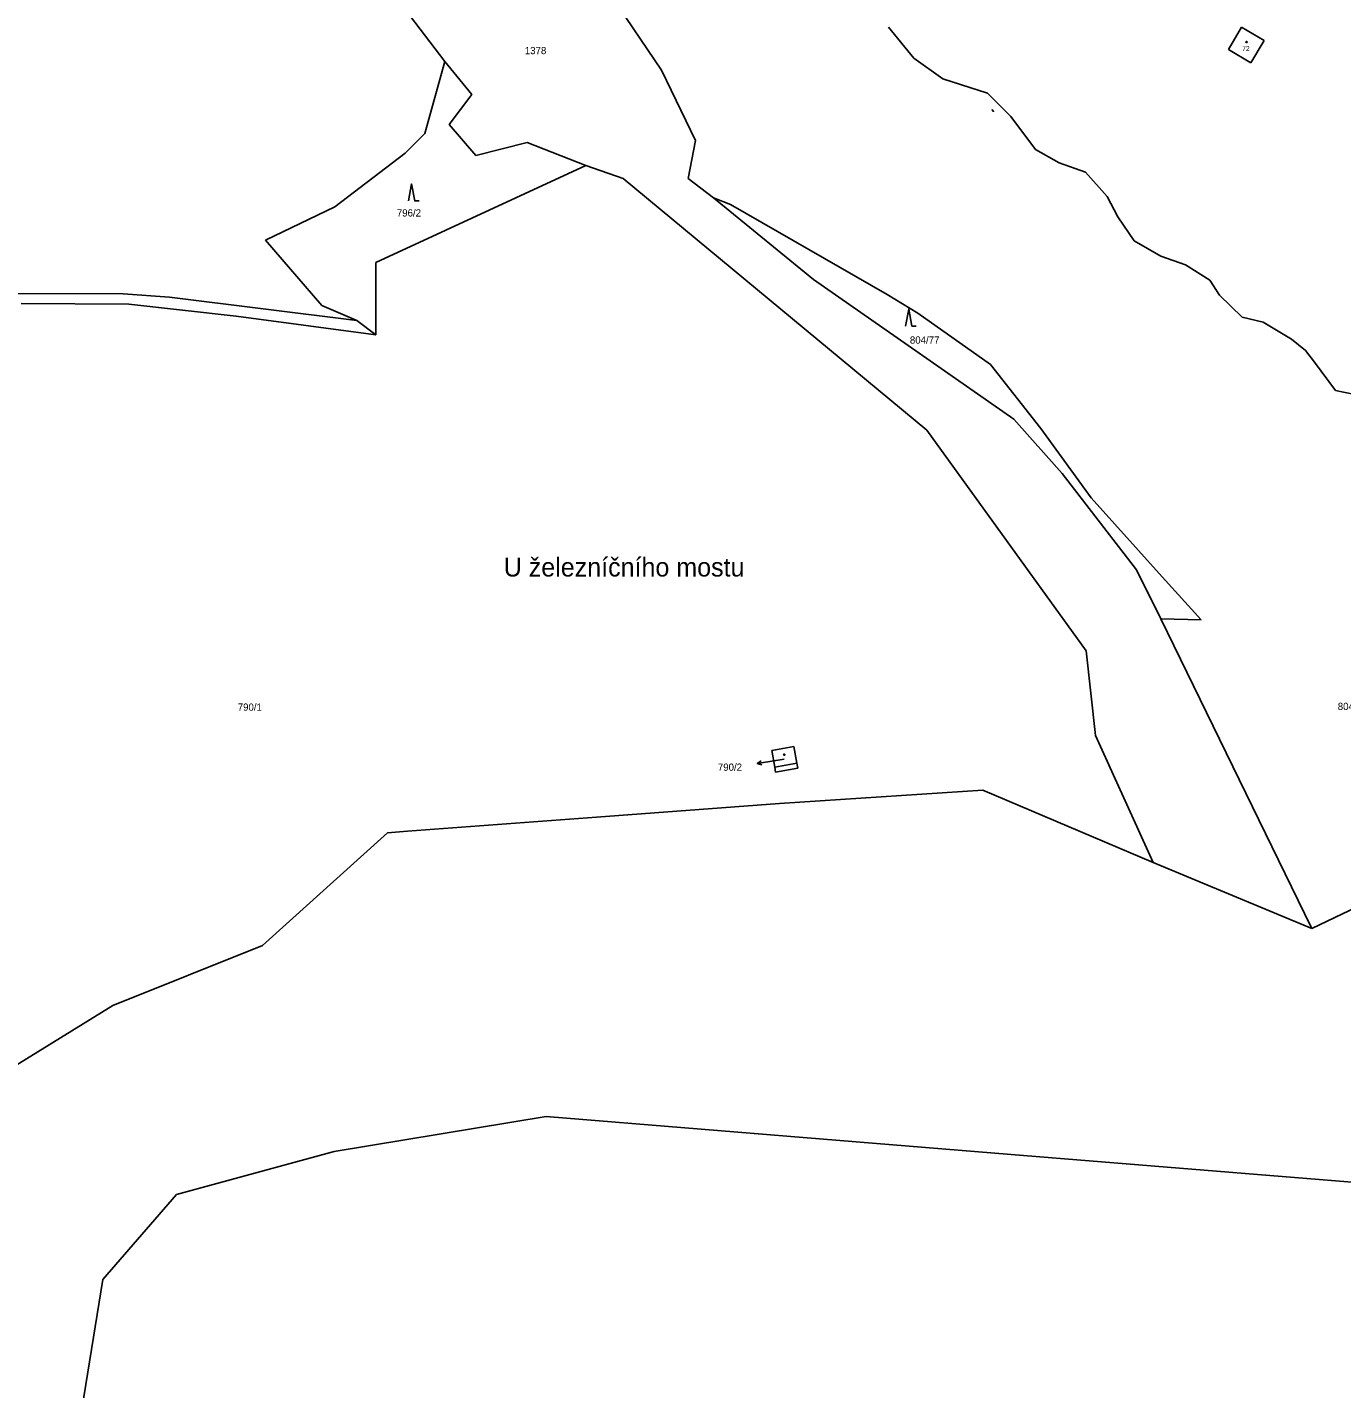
# Model space of a CAD drawing. Extents: x -852001 to -842497, y -1063614 to -1052182.
# Drawn here: x -843659.2 to -843350.2, y -1062182 to -1061862.1 of the extents above; entities that cross this region are included whole.
import ezdxf

# ---------------------------------------------------------------- set-up
doc = ezdxf.new("R2010")
doc.units = 0
for name, color, linetype in [('Default', 7, 'Continuous'), ('KN_HRANICE', 7, 'Continuous'), ('KN_KULTURY', 7, 'Continuous'), ('KN_PARCELY', 7, 'Continuous'), ('KN_SLUCKY', 7, 'Continuous')]:
    doc.layers.add(name, color=color, linetype=linetype)

# ---------------------------------------------------------------- blocks, each defined once
blk = doc.blocks.new('308')
at = {"layer": 'Default'}
blk.add_lwpolyline([(-0.75, 0), (0, 4), (0.75, 0), (1.75, 0)], dxfattribs=at)
blk = doc.blocks.new('10292')
at = {"layer": 'Default'}
blk.add_line((0, 3), (0, 0), dxfattribs=at)
blk.add_lwpolyline([(-0.5, 2), (0, 3), (0.5, 2)], dxfattribs=at)
blk = doc.blocks.new('1060')
at = {"layer": 'Default'}
blk.add_line((-0.3, 0), (0.3, 0), dxfattribs=at)
blk.add_lwpolyline([(0.18, 0.04), (0.3, 0), (0.18, -0.04)], dxfattribs=at)
blk = doc.blocks.new('402')
at = {"layer": 'Default'}
blk.add_lwpolyline([(0.09, 0.15), (0.18, 0), (0.09, -0.15), (-0.09, -0.15), (-0.18, 0), (-0.09, 0.15), (0.09, 0.15)], dxfattribs=at)

msp = doc.modelspace()

# ---------------------------------------------------------------- linework, layer by layer
at = {"layer": 'KN_HRANICE'}
for p, q in [((-843575.5, -1061851.1), (-843561, -1061870.14)), ((-843575.5, -1061851.1), (-843561, -1061870.14)), ((-843510.14, -1061872.13), (-843523.95, -1061851.73)), ((-843510.14, -1061872.13), (-843523.95, -1061851.73)), ((-843373.8, -1061862.07), (-843376.87, -1061867.27)), ((-843373.8, -1061862.07), (-843376.87, -1061867.27)), ((-843368.5, -1061865.2), (-843373.8, -1061862.07)), ((-843368.5, -1061865.2), (-843373.8, -1061862.07)), ((-843371.59, -1061870.39), (-843368.5, -1061865.2)), ((-843371.59, -1061870.39), (-843368.5, -1061865.2)), ((-843376.87, -1061867.27), (-843371.59, -1061870.39)), ((-843376.87, -1061867.27), (-843371.59, -1061870.39)), ((-843561, -1061870.14), (-843565.72, -1061887.02)), ((-843561, -1061870.14), (-843565.72, -1061887.02)), ((-843561, -1061870.14), (-843554.72, -1061877.9)), ((-843561, -1061870.14), (-843554.72, -1061877.9)), ((-843502.1, -1061888.66), (-843510.14, -1061872.13)), ((-843502.1, -1061888.66), (-843510.14, -1061872.13)), ((-843554.72, -1061877.9), (-843560.02, -1061884.93)), ((-843554.72, -1061877.9), (-843560.02, -1061884.93)), ((-843565.72, -1061887.02), (-843570.36, -1061891.66)), ((-843565.72, -1061887.02), (-843570.36, -1061891.66)), ((-843560.02, -1061884.93), (-843553.73, -1061892.2)), ((-843560.02, -1061884.93), (-843553.73, -1061892.2)), ((-843553.73, -1061892.2), (-843541.66, -1061889.12)), ((-843553.73, -1061892.2), (-843541.66, -1061889.12)), ((-843541.66, -1061889.12), (-843527.86, -1061894.54)), ((-843541.66, -1061889.12), (-843527.86, -1061894.54)), ((-843503.85, -1061897.57), (-843502.1, -1061888.66)), ((-843503.85, -1061897.57), (-843502.1, -1061888.66)), ((-843570.36, -1061891.66), (-843586.92, -1061904.25)), ((-843570.36, -1061891.66), (-843586.92, -1061904.25)), ((-843577.25, -1061917.38), (-843527.86, -1061894.54)), ((-843577.25, -1061917.38), (-843527.86, -1061894.54)), ((-843527.86, -1061894.54), (-843519.11, -1061897.62)), ((-843527.86, -1061894.54), (-843519.11, -1061897.62)), ((-843497.88, -1061902.17), (-843503.85, -1061897.57)), ((-843497.88, -1061902.17), (-843503.85, -1061897.57)), ((-843519.11, -1061897.62), (-843447.74, -1061956.71)), ((-843519.11, -1061897.62), (-843447.74, -1061956.71)), ((-843474.38, -1061921.33), (-843497.88, -1061902.17)), ((-843497.88, -1061902.17), (-843493.89, -1061903.71)), ((-843474.38, -1061921.33), (-843497.88, -1061902.17)), ((-843497.88, -1061902.17), (-843493.89, -1061903.71)), ((-843493.89, -1061903.71), (-843457.08, -1061924.86)), ((-843493.89, -1061903.71), (-843457.08, -1061924.86)), ((-843586.92, -1061904.25), (-843603.22, -1061912.07)), ((-843586.92, -1061904.25), (-843603.22, -1061912.07)), ((-843603.22, -1061912.07), (-843589.97, -1061927.45)), ((-843603.22, -1061912.07), (-843589.97, -1061927.45)), ((-843577.26, -1061934.32), (-843577.25, -1061917.38)), ((-843577.26, -1061934.32), (-843577.25, -1061917.38)), ((-843427.27, -1061954.14), (-843474.38, -1061921.33)), ((-843427.27, -1061954.14), (-843474.38, -1061921.33)), ((-843636.67, -1061924.71), (-843677.25, -1061924.62)), ((-843636.67, -1061924.71), (-843677.25, -1061924.62)), ((-843625.73, -1061925.47), (-843636.67, -1061924.71)), ((-843625.73, -1061925.47), (-843636.67, -1061924.71)), ((-843581.73, -1061930.99), (-843625.73, -1061925.47)), ((-843581.73, -1061930.99), (-843625.73, -1061925.47)), ((-843457.08, -1061924.86), (-843449.87, -1061929.22)), ((-843457.08, -1061924.86), (-843449.87, -1061929.22)), ((-843660.62, -1061927.01), (-843635.34, -1061927.1)), ((-843660.62, -1061927.01), (-843635.34, -1061927.1)), ((-843635.34, -1061927.1), (-843610.04, -1061929.96)), ((-843635.34, -1061927.1), (-843610.04, -1061929.96)), ((-843589.97, -1061927.45), (-843581.73, -1061930.99)), ((-843589.97, -1061927.45), (-843581.73, -1061930.99)), ((-843449.87, -1061929.22), (-843432.83, -1061941.28)), ((-843449.87, -1061929.22), (-843432.83, -1061941.28)), ((-843610.04, -1061929.96), (-843577.26, -1061934.32)), ((-843610.04, -1061929.96), (-843577.26, -1061934.32)), ((-843577.26, -1061934.32), (-843581.73, -1061930.99)), ((-843577.26, -1061934.32), (-843581.73, -1061930.99)), ((-843432.83, -1061941.28), (-843420.93, -1061956.38)), ((-843432.83, -1061941.28), (-843420.93, -1061956.38)), ((-843415.95, -1061966.96), (-843427.27, -1061954.14)), ((-843415.95, -1061966.96), (-843427.27, -1061954.14)), ((-843447.74, -1061956.71), (-843410.34, -1062008.61)), ((-843447.74, -1061956.71), (-843410.34, -1062008.61)), ((-843420.93, -1061956.38), (-843409.12, -1061972.68)), ((-843420.93, -1061956.38), (-843409.12, -1061972.68)), ((-843398.44, -1061989.53), (-843415.95, -1061966.96)), ((-843398.44, -1061989.53), (-843415.95, -1061966.96)), ((-843409.12, -1061972.68), (-843392.46, -1061991.22)), ((-843409.12, -1061972.68), (-843392.46, -1061991.22)), ((-843392.79, -1062001.1), (-843398.44, -1061989.53)), ((-843392.79, -1062001.1), (-843398.44, -1061989.53)), ((-843392.46, -1061991.22), (-843383.26, -1062001.29)), ((-843392.46, -1061991.22), (-843383.26, -1062001.29)), ((-843357.43, -1062073.51), (-843392.79, -1062001.1)), ((-843383.26, -1062001.29), (-843392.79, -1062001.1)), ((-843357.43, -1062073.51), (-843392.79, -1062001.1)), ((-843383.26, -1062001.29), (-843392.79, -1062001.1)), ((-843410.34, -1062008.61), (-843408.1, -1062028.48)), ((-843410.34, -1062008.61), (-843408.1, -1062028.48)), ((-843408.1, -1062028.48), (-843394.55, -1062058.3)), ((-843408.1, -1062028.48), (-843394.55, -1062058.3)), ((-843484.2, -1062031.99), (-843478.99, -1062031.04)), ((-843484.2, -1062031.99), (-843478.99, -1062031.04)), ((-843478.99, -1062031.04), (-843478.31, -1062034.99)), ((-843478.99, -1062031.04), (-843478.31, -1062034.99)), ((-843483.48, -1062035.92), (-843484.2, -1062031.99)), ((-843483.48, -1062035.92), (-843484.2, -1062031.99)), ((-843478.31, -1062034.99), (-843478.1, -1062036.2)), ((-843478.31, -1062034.99), (-843478.1, -1062036.2)), ((-843483.29, -1062037.13), (-843483.48, -1062035.92)), ((-843483.29, -1062037.13), (-843483.48, -1062035.92)), ((-843478.1, -1062036.2), (-843483.29, -1062037.13)), ((-843478.1, -1062036.2), (-843483.29, -1062037.13)), ((-843434.57, -1062041.33), (-843482.38, -1062044.5)), ((-843434.57, -1062041.33), (-843482.38, -1062044.5)), ((-843394.55, -1062058.3), (-843434.57, -1062041.33)), ((-843394.55, -1062058.3), (-843434.57, -1062041.33)), ((-843482.38, -1062044.5), (-843525.38, -1062047.66)), ((-843482.38, -1062044.5), (-843525.38, -1062047.66)), ((-843525.38, -1062047.66), (-843569.83, -1062051)), ((-843525.38, -1062047.66), (-843569.83, -1062051)), ((-843569.83, -1062051), (-843574.5, -1062051.35)), ((-843569.83, -1062051), (-843574.5, -1062051.35)), ((-843304, -1062048.33), (-843357.26, -1062073.88)), ((-843304, -1062048.33), (-843357.26, -1062073.88)), ((-843574.5, -1062051.35), (-843603.92, -1062077.87)), ((-843574.5, -1062051.35), (-843603.92, -1062077.87)), ((-843357.26, -1062073.88), (-843394.55, -1062058.3)), ((-843357.26, -1062073.88), (-843394.55, -1062058.3)), ((-843357.26, -1062073.88), (-843357.43, -1062073.51)), ((-843357.26, -1062073.88), (-843357.43, -1062073.51)), ((-843603.92, -1062077.87), (-843639.07, -1062091.95)), ((-843603.92, -1062077.87), (-843639.07, -1062091.95)), ((-843639.07, -1062091.95), (-843668.06, -1062109.81)), ((-843639.07, -1062091.95), (-843668.06, -1062109.81)), ((-843587.08, -1062126.23), (-843537.23, -1062118.05)), ((-843587.08, -1062126.23), (-843537.23, -1062118.05)), ((-843537.23, -1062118.05), (-843427.91, -1062126.94)), ((-843537.23, -1062118.05), (-843427.91, -1062126.94)), ((-843624.14, -1062136.31), (-843587.08, -1062126.23)), ((-843624.14, -1062136.31), (-843587.08, -1062126.23)), ((-843427.91, -1062126.94), (-843319.99, -1062135.71)), ((-843427.91, -1062126.94), (-843319.99, -1062135.71)), ((-843641.42, -1062156.35), (-843624.14, -1062136.31)), ((-843641.42, -1062156.35), (-843624.14, -1062136.31)), ((-843651.36, -1062217.31), (-843641.42, -1062156.35)), ((-843651.36, -1062217.31), (-843641.42, -1062156.35))]:
    msp.add_line(p, q, dxfattribs=at)
at = {"layer": 'KN_PARCELY'}
msp.add_line((-843481.26, -1062034.04), (-843484.66, -1062034.6), dxfattribs=at)
msp.add_line((-843481.26, -1062034.04), (-843484.66, -1062034.6), dxfattribs=at)
at = {"layer": 'KN_SLUCKY'}
for p, q in [((-843456.76, -1061862.05), (-843450.82, -1061869.35)), ((-843456.76, -1061862.05), (-843450.82, -1061869.35)), ((-843450.82, -1061869.35), (-843443.98, -1061874.22)), ((-843450.82, -1061869.35), (-843443.98, -1061874.22)), ((-843443.98, -1061874.22), (-843433.48, -1061877.57)), ((-843443.98, -1061874.22), (-843433.48, -1061877.57)), ((-843433.48, -1061877.57), (-843428, -1061883.05)), ((-843433.48, -1061877.57), (-843428, -1061883.05)), ((-843428, -1061883.05), (-843422.22, -1061890.82)), ((-843428, -1061883.05), (-843422.22, -1061890.82)), ((-843422.22, -1061890.82), (-843416.67, -1061893.96)), ((-843422.22, -1061890.82), (-843416.67, -1061893.96)), ((-843416.67, -1061893.96), (-843410.43, -1061896.09)), ((-843416.67, -1061893.96), (-843410.43, -1061896.09)), ((-843410.43, -1061896.09), (-843405.41, -1061901.87)), ((-843410.43, -1061896.09), (-843405.41, -1061901.87)), ((-843405.41, -1061901.87), (-843402.83, -1061906.59)), ((-843405.41, -1061901.87), (-843402.83, -1061906.59)), ((-843402.83, -1061906.59), (-843399.02, -1061912.22)), ((-843402.83, -1061906.59), (-843399.02, -1061912.22)), ((-843399.02, -1061912.22), (-843392.78, -1061915.88)), ((-843399.02, -1061912.22), (-843392.78, -1061915.88)), ((-843392.78, -1061915.88), (-843387, -1061917.86)), ((-843392.78, -1061915.88), (-843387, -1061917.86)), ((-843387, -1061917.86), (-843381.22, -1061921.51)), ((-843387, -1061917.86), (-843381.22, -1061921.51)), ((-843381.22, -1061921.51), (-843378.94, -1061925.01)), ((-843381.22, -1061921.51), (-843378.94, -1061925.01)), ((-843378.94, -1061925.01), (-843373.61, -1061930.19)), ((-843378.94, -1061925.01), (-843373.61, -1061930.19)), ((-843373.61, -1061930.19), (-843368.74, -1061931.4)), ((-843373.61, -1061930.19), (-843368.74, -1061931.4)), ((-843368.74, -1061931.4), (-843362.05, -1061935.36)), ((-843368.74, -1061931.4), (-843362.05, -1061935.36)), ((-843362.05, -1061935.36), (-843358.74, -1061938.03)), ((-843362.05, -1061935.36), (-843358.74, -1061938.03)), ((-843358.74, -1061938.03), (-843356.61, -1061940.77)), ((-843358.74, -1061938.03), (-843356.61, -1061940.77)), ((-843356.61, -1061940.77), (-843351.74, -1061947.46)), ((-843356.61, -1061940.77), (-843351.74, -1061947.46)), ((-843351.74, -1061947.46), (-843344.89, -1061948.83)), ((-843351.74, -1061947.46), (-843344.89, -1061948.83)), ((-843483.48, -1062035.92), (-843478.31, -1062034.99)), ((-843483.48, -1062035.92), (-843478.31, -1062034.99))]:
    msp.add_line(p, q, dxfattribs=at)

# ---------------------------------------------------------------- block references
at = {"layer": 'KN_KULTURY'}
for name, p in [('402', (-843372.61, -1061865.53)), ('402', (-843372.61, -1061865.53)), ('308', (-843568.85, -1061902.89)), ('308', (-843568.85, -1061902.89)), ('308', (-843452.02, -1061932.28)), ('308', (-843452.02, -1061932.28)), ('402', (-843481.26, -1062033)), ('402', (-843481.26, -1062033))]:
    msp.add_blockref(name, p, dxfattribs=at)
at = {"layer": 'KN_PARCELY'}
for name, p, rotation in [('1060', (-843432.29, -1061881.63), -46.07642400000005), ('1060', (-843432.29, -1061881.63), -46.07642400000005), ('10292', (-843484.66, -1062034.6), 99.29358599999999), ('10292', (-843484.66, -1062034.6), 99.29358599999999)]:
    msp.add_blockref(name, p, dxfattribs=dict(at, rotation=rotation))

# ---------------------------------------------------------------- texts
for s, height, p in [('1378', 1.7, (-843542.24, -1061868.39)), ('1378', 1.7, (-843542.24, -1061868.39)), ('72', 1.14, (-843373.64, -1061867.65)), ('72', 1.14, (-843373.64, -1061867.65)), ('796/2', 1.7, (-843572.32, -1061906.54)), ('796/2', 1.7, (-843572.32, -1061906.54)), ('804/77', 1.7, (-843451.74, -1061936.41)), ('804/77', 1.7, (-843451.74, -1061936.41)), ('U železníčního mostu', 4.4, (-843547.19, -1061991.13)), ('U železníčního mostu', 4.4, (-843547.19, -1061991.13)), ('790/1', 1.7, (-843609.72, -1062022.67)), ('790/1', 1.7, (-843609.72, -1062022.67)), ('804/33', 1.7, (-843351.18, -1062022.5)), ('804/33', 1.7, (-843351.18, -1062022.5)), ('790/2', 1.7, (-843496.87, -1062036.78)), ('790/2', 1.7, (-843496.87, -1062036.78)), ('790/2', 0.1, (-843481.5, -1062034.04)), ('790/2', 0.1, (-843481.5, -1062034.04))]:
    msp.add_text(s, height=height, dxfattribs=at).set_placement(p)

doc.saveas('drawing.dxf')
